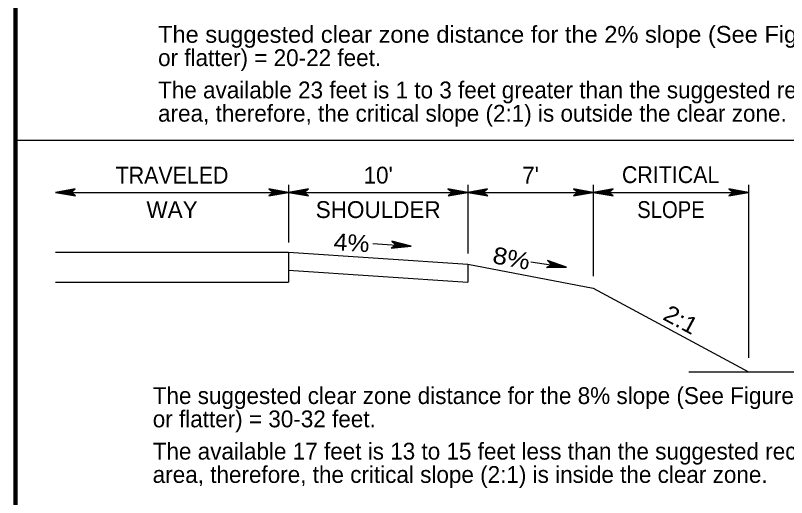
# Model space of a CAD drawing. Extents: x -15.691 to -15.016, y -14.8 to -13.916.
# Drawn here: x -15.6451 to -15.2866, y -14.3626 to -14.1387 of the extents above; entities that cross this region are included whole.
import ezdxf
from ezdxf.enums import TextEntityAlignment as Align

# ---------------------------------------------------------------- set-up
doc = ezdxf.new("R2010")
doc.units = 0
doc.header["$LTSCALE"] = 0.0031
for name, color, linetype, lineweight in [('1', 7, 'Continuous', 90), ('24', 7, 'Continuous', 25), ('5', 7, 'Continuous', 25)]:
    doc.layers.add(name, color=color, linetype=linetype, lineweight=lineweight)

msp = doc.modelspace()

# ---------------------------------------------------------------- linework, layer by layer
at = {"layer": '1'}
msp.add_line((-15.645142, -14.753775), (-15.645142, -13.962108), dxfattribs=at)
msp.add_line((-15.645142, -14.753775), (-15.645142, -13.962108), dxfattribs=at)
at = {"layer": '24'}
for p, q in [((-15.518158, -14.217367), (-15.518158, -14.244108)), ((-15.434825, -14.217367), (-15.434825, -14.249208)), ((-15.376492, -14.217367), (-15.376492, -14.259825)), ((-15.304267, -14.217367), (-15.304267, -14.297608)), ((-15.626492, -14.220833), (-15.518158, -14.220833)), ((-15.478925, -14.244533), (-15.4611, -14.245808)), ((-15.405475, -14.253025), (-15.388925, -14.255617))]:
    msp.add_line(p, q, dxfattribs=at)
for points in [[(-15.626492, -14.220833), (-15.61725, -14.222467), (-15.619458, -14.220833), (-15.6173, -14.219225), (-15.626492, -14.220833), (-15.625875, -14.220817), (-15.617508, -14.222342), (-15.619633, -14.220817), (-15.617675, -14.21935), (-15.62555, -14.220783), (-15.625242, -14.220833), (-15.618075, -14.222108), (-15.619683, -14.220817), (-15.618025, -14.219558), (-15.6251, -14.220833), (-15.624792, -14.220783), (-15.618525, -14.221917), (-15.619742, -14.220833), (-15.6185, -14.219708), (-15.6239, -14.220783), (-15.623375, -14.220783), (-15.618992, -14.221683), (-15.619842, -14.220858), (-15.618925, -14.219942), (-15.623283, -14.220833), (-15.622792, -14.220858), (-15.619492, -14.221425), (-15.620125, -14.220783), (-15.619442, -14.22015), (-15.622342, -14.220833), (-15.621875, -14.220883), (-15.619892, -14.221258), (-15.620217, -14.220817), (-15.619675, -14.220317), (-15.621633, -14.220833), (-15.620342, -14.221142), (-15.620525, -14.220783), (-15.619958, -14.220433), (-15.621308, -14.220783), (-15.620458, -14.221), (-15.620817, -14.220717), (-15.620408, -14.22055), (-15.620817, -14.220817), (-15.6206, -14.220858)], [(-15.518158, -14.220833), (-15.5274, -14.2192), (-15.525192, -14.220833), (-15.52735, -14.222442), (-15.518158, -14.220833), (-15.518775, -14.22085), (-15.527142, -14.219317), (-15.525017, -14.22085), (-15.526975, -14.222317), (-15.5191, -14.220875), (-15.519408, -14.220833), (-15.526583, -14.219558), (-15.524975, -14.22085), (-15.526625, -14.222108), (-15.51955, -14.220833), (-15.519858, -14.220875), (-15.526125, -14.21975), (-15.524908, -14.220833), (-15.52615, -14.221958), (-15.52075, -14.220883), (-15.521275, -14.220875), (-15.525658, -14.219983), (-15.524808, -14.220808), (-15.525725, -14.221725), (-15.521367, -14.220833), (-15.521858, -14.220808), (-15.525158, -14.220242), (-15.524525, -14.220883), (-15.525208, -14.221508), (-15.522317, -14.220833), (-15.522775, -14.220783), (-15.524758, -14.220408), (-15.524433, -14.22085), (-15.524975, -14.22135), (-15.523017, -14.220833), (-15.524308, -14.220525), (-15.524125, -14.220875), (-15.524692, -14.221233), (-15.523342, -14.220883), (-15.524192, -14.220667), (-15.523833, -14.22095), (-15.524242, -14.221117), (-15.523842, -14.22085), (-15.52405, -14.220808)], [(-15.518158, -14.220833), (-15.508917, -14.222467), (-15.511125, -14.220833), (-15.508967, -14.219225), (-15.518158, -14.220833), (-15.517542, -14.220817), (-15.509175, -14.222342), (-15.5113, -14.220817), (-15.509342, -14.21935), (-15.517217, -14.220783), (-15.516908, -14.220833), (-15.509742, -14.222108), (-15.51135, -14.220817), (-15.509692, -14.219558), (-15.516767, -14.220833), (-15.516458, -14.220783), (-15.510192, -14.221917), (-15.511408, -14.220833), (-15.510167, -14.219708), (-15.515567, -14.220783), (-15.515042, -14.220783), (-15.510658, -14.221683), (-15.511508, -14.220858), (-15.510592, -14.219942), (-15.51495, -14.220833), (-15.514458, -14.220858), (-15.511158, -14.221425), (-15.511792, -14.220783), (-15.511108, -14.22015), (-15.514008, -14.220833), (-15.513542, -14.220883), (-15.511558, -14.221258), (-15.511883, -14.220817), (-15.511342, -14.220317), (-15.5133, -14.220833), (-15.512008, -14.221142), (-15.512192, -14.220783), (-15.511625, -14.220433), (-15.512975, -14.220783), (-15.512125, -14.221), (-15.512483, -14.220717), (-15.512075, -14.22055), (-15.512475, -14.220817), (-15.512267, -14.220858)], [(-15.518158, -14.220833), (-15.434825, -14.220833), (-15.376492, -14.220833), (-15.304267, -14.220833)], [(-15.434825, -14.220833), (-15.444067, -14.2192), (-15.441858, -14.220833), (-15.444017, -14.222442), (-15.434825, -14.220833), (-15.435442, -14.22085), (-15.443808, -14.219317), (-15.441683, -14.22085), (-15.443642, -14.222317), (-15.435767, -14.220875), (-15.436075, -14.220833), (-15.44325, -14.219558), (-15.441642, -14.22085), (-15.443292, -14.222108), (-15.436217, -14.220833), (-15.436525, -14.220875), (-15.442792, -14.21975), (-15.441575, -14.220833), (-15.442817, -14.221958), (-15.437417, -14.220883), (-15.437942, -14.220875), (-15.442325, -14.219983), (-15.441475, -14.220808), (-15.442392, -14.221725), (-15.438033, -14.220833), (-15.438525, -14.220808), (-15.441825, -14.220242), (-15.441192, -14.220883), (-15.441875, -14.221508), (-15.438983, -14.220833), (-15.439442, -14.220783), (-15.441425, -14.220408), (-15.4411, -14.22085), (-15.441642, -14.22135), (-15.439683, -14.220833), (-15.440975, -14.220525), (-15.440792, -14.220875), (-15.441358, -14.221233), (-15.440008, -14.220883), (-15.440858, -14.220667), (-15.4405, -14.22095), (-15.440908, -14.221117), (-15.440508, -14.22085), (-15.440717, -14.220808)], [(-15.434825, -14.220833), (-15.425583, -14.222467), (-15.427792, -14.220833), (-15.425633, -14.219225), (-15.434825, -14.220833), (-15.434208, -14.220817), (-15.425842, -14.222342), (-15.427967, -14.220817), (-15.426008, -14.21935), (-15.433883, -14.220783), (-15.433575, -14.220833), (-15.426408, -14.222108), (-15.428017, -14.220817), (-15.426358, -14.219558), (-15.433433, -14.220833), (-15.433125, -14.220783), (-15.426858, -14.221917), (-15.428075, -14.220833), (-15.426833, -14.219708), (-15.432233, -14.220783), (-15.431708, -14.220783), (-15.427325, -14.221683), (-15.428175, -14.220858), (-15.427258, -14.219942), (-15.431617, -14.220833), (-15.431125, -14.220858), (-15.427825, -14.221425), (-15.428458, -14.220783), (-15.427775, -14.22015), (-15.430675, -14.220833), (-15.430208, -14.220883), (-15.428225, -14.221258), (-15.42855, -14.220817), (-15.428008, -14.220317), (-15.429967, -14.220833), (-15.428675, -14.221142), (-15.428858, -14.220783), (-15.428292, -14.220433), (-15.429642, -14.220783), (-15.428792, -14.221), (-15.42915, -14.220717), (-15.428742, -14.22055), (-15.429142, -14.220817), (-15.428933, -14.220858)], [(-15.376492, -14.220833), (-15.385733, -14.2192), (-15.383525, -14.220833), (-15.385683, -14.222442), (-15.376492, -14.220833), (-15.377108, -14.22085), (-15.385475, -14.219317), (-15.38335, -14.22085), (-15.385308, -14.222317), (-15.377433, -14.220875), (-15.377742, -14.220833), (-15.384917, -14.219558), (-15.383308, -14.22085), (-15.384958, -14.222108), (-15.377883, -14.220833), (-15.378192, -14.220875), (-15.384458, -14.21975), (-15.383242, -14.220833), (-15.384483, -14.221958), (-15.379083, -14.220883), (-15.379608, -14.220875), (-15.383992, -14.219983), (-15.383142, -14.220808), (-15.384058, -14.221725), (-15.3797, -14.220833), (-15.380192, -14.220808), (-15.383492, -14.220242), (-15.382858, -14.220883), (-15.383542, -14.221508), (-15.38065, -14.220833), (-15.381108, -14.220783), (-15.383092, -14.220408), (-15.382767, -14.22085), (-15.383308, -14.22135), (-15.38135, -14.220833), (-15.382642, -14.220525), (-15.382458, -14.220875), (-15.383025, -14.221233), (-15.381675, -14.220883), (-15.382525, -14.220667), (-15.382167, -14.22095), (-15.382575, -14.221117), (-15.382175, -14.22085), (-15.382383, -14.220808)], [(-15.376492, -14.220833), (-15.36725, -14.222467), (-15.369458, -14.220833), (-15.3673, -14.219225), (-15.376492, -14.220833), (-15.375875, -14.220817), (-15.367508, -14.222342), (-15.369633, -14.220817), (-15.367675, -14.21935), (-15.37555, -14.220783), (-15.375242, -14.220833), (-15.368075, -14.222108), (-15.369683, -14.220817), (-15.368025, -14.219558), (-15.3751, -14.220833), (-15.374792, -14.220783), (-15.368525, -14.221917), (-15.369742, -14.220833), (-15.3685, -14.219708), (-15.3739, -14.220783), (-15.373375, -14.220783), (-15.368992, -14.221683), (-15.369842, -14.220858), (-15.368925, -14.219942), (-15.373283, -14.220833), (-15.372792, -14.220858), (-15.369492, -14.221425), (-15.370125, -14.220783), (-15.369442, -14.22015), (-15.372342, -14.220833), (-15.371875, -14.220883), (-15.369892, -14.221258), (-15.370217, -14.220817), (-15.369675, -14.220317), (-15.371633, -14.220833), (-15.370342, -14.221142), (-15.370525, -14.220783), (-15.369958, -14.220433), (-15.371308, -14.220783), (-15.370458, -14.221), (-15.370817, -14.220717), (-15.370408, -14.22055), (-15.370808, -14.220817), (-15.3706, -14.220858)], [(-15.304267, -14.220833), (-15.313508, -14.2192), (-15.3113, -14.220833), (-15.313467, -14.222442), (-15.304267, -14.220833), (-15.304883, -14.22085), (-15.31325, -14.219317), (-15.311133, -14.22085), (-15.313092, -14.222317), (-15.305217, -14.220875), (-15.305525, -14.220833), (-15.312692, -14.219558), (-15.311083, -14.22085), (-15.312733, -14.222108), (-15.305667, -14.220833), (-15.305967, -14.220875), (-15.312233, -14.21975), (-15.311017, -14.220833), (-15.312258, -14.221958), (-15.306867, -14.220883), (-15.307383, -14.220875), (-15.311775, -14.219983), (-15.310917, -14.220808), (-15.311833, -14.221725), (-15.307475, -14.220833), (-15.307975, -14.220808), (-15.311267, -14.220242), (-15.310633, -14.220883), (-15.311325, -14.221508), (-15.308425, -14.220833), (-15.308892, -14.220783), (-15.310867, -14.220408), (-15.310542, -14.22085), (-15.311083, -14.22135), (-15.309133, -14.220833), (-15.310425, -14.220525), (-15.310233, -14.220875), (-15.3108, -14.221233), (-15.309458, -14.220883), (-15.3103, -14.220667), (-15.30995, -14.22095), (-15.310358, -14.221117), (-15.30995, -14.22085), (-15.310167, -14.220808)], [(-15.4611, -14.245808), (-15.4702, -14.243525), (-15.468108, -14.245308), (-15.470383, -14.246758), (-15.4611, -14.245808), (-15.461708, -14.245783), (-15.46995, -14.243658), (-15.467942, -14.245342), (-15.47, -14.246658), (-15.462042, -14.245792), (-15.46235, -14.245725), (-15.469408, -14.243942), (-15.467892, -14.245342), (-15.469633, -14.246475), (-15.462483, -14.245708), (-15.4628, -14.245733), (-15.468967, -14.244158), (-15.467825, -14.245333), (-15.46915, -14.246367), (-15.463683, -14.245675), (-15.464208, -14.245633), (-15.468517, -14.244425), (-15.467725, -14.245308), (-15.468708, -14.246158), (-15.464292, -14.245583), (-15.464783, -14.245517), (-15.468033, -14.244717), (-15.46745, -14.245408), (-15.468183, -14.245983), (-15.465242, -14.245517), (-15.4657, -14.245433), (-15.46765, -14.244917), (-15.467358, -14.245383), (-15.467933, -14.245833), (-15.465942, -14.245467), (-15.467208, -14.245067), (-15.46705, -14.245433), (-15.467642, -14.245742), (-15.466275, -14.245492), (-15.4671, -14.245217), (-15.466767, -14.245517), (-15.467183, -14.245658), (-15.466767, -14.245425), (-15.466975, -14.245367)], [(-15.388917, -14.255575), (-15.3978, -14.252533), (-15.395867, -14.254492), (-15.39825, -14.255742), (-15.388917, -14.255575), (-15.389533, -14.2555), (-15.397558, -14.252692), (-15.3957, -14.254533), (-15.397858, -14.255675), (-15.389858, -14.255475), (-15.390158, -14.255383), (-15.397042, -14.253017), (-15.39565, -14.254542), (-15.397483, -14.255525), (-15.3903, -14.255358), (-15.390608, -14.255358), (-15.396625, -14.253275), (-15.395583, -14.254533), (-15.396992, -14.255458), (-15.391492, -14.255225), (-15.392, -14.255142), (-15.3962, -14.253575), (-15.395483, -14.254525), (-15.396533, -14.255292), (-15.392092, -14.255083), (-15.392575, -14.254975), (-15.395742, -14.253908), (-15.395217, -14.254642), (-15.395992, -14.255158), (-15.393025, -14.254933), (-15.393475, -14.254817), (-15.395375, -14.254133), (-15.395125, -14.254625), (-15.395733, -14.255033), (-15.393725, -14.254825), (-15.39495, -14.254325), (-15.394825, -14.2547), (-15.395433, -14.254958), (-15.39405, -14.254825), (-15.394858, -14.254483), (-15.39455, -14.254808), (-15.394975, -14.254917), (-15.394533, -14.254717), (-15.394742, -14.254642)]]:
    msp.add_lwpolyline(points, dxfattribs=at)
at = {"layer": '5'}
for p, q in [((-15.645142, -14.196558), (-15.061808, -14.196558)), ((-15.626492, -14.248608), (-15.518158, -14.248608)), ((-15.518158, -14.248608), (-15.518158, -14.2625)), ((-15.434825, -14.254167), (-15.434825, -14.262517)), ((-15.518158, -14.256958), (-15.434825, -14.262517)), ((-15.626492, -14.2625), (-15.518158, -14.2625)), ((-15.33205, -14.304167), (-15.304267, -14.304167)), ((-15.304267, -14.304167), (-15.276492, -14.304167))]:
    msp.add_line(p, q, dxfattribs=at)
msp.add_lwpolyline([(-15.518158, -14.248608), (-15.434825, -14.254167), (-15.376492, -14.265275), (-15.304267, -14.304167)], dxfattribs=at)

# ---------------------------------------------------------------- texts
at = {"layer": '1', "width": 1.05}
msp.add_text('The suggested clear zone distance for the 2% slope (See Figure 8-A, Cut Slope, 6:1', height=0.007817, dxfattribs=at).set_placement((-15.578825, -14.151367))
at = {"layer": '1'}
for s, p in [('or flatter) = 20-22 feet.', (-15.578825, -14.162183)), ('The available 23 feet is 1 to 3 feet greater than the suggested recovery', (-15.578825, -14.177183)), ('area, therefore, the critical slope (2:1) is outside the clear zone.', (-15.578825, -14.188)), ('The suggested clear zone distance for the 8% slope (See Figure 8-A, Fill Slope, 6:1', (-15.581308, -14.319125)), ('or flatter) = 30-32 feet.', (-15.581308, -14.329942)), ('The available 17 feet is 13 to 15 feet less than the suggested recovery', (-15.581308, -14.344942)), ('area, therefore, the critical slope (2:1) is inside the clear zone.', (-15.581308, -14.355758))]:
    msp.add_text(s, height=0.007817, dxfattribs=at).set_placement(p)
for s, width, p in [('TRAVELED', 0.95, (-15.572321, -14.216742)), ('CRITICAL', 0.95, (-15.340533, -14.216517)), ('SLOPE', 0.9, (-15.340383, -14.232742))]:
    msp.add_text(s, height=0.007817, dxfattribs=dict(at, width=width)).set_placement(p, align=Align.CENTER)
for s, p in [("10'", (-15.476496, -14.216742)), ("7'", (-15.405658, -14.216742)), ('WAY', (-15.572321, -14.232742)), ('SHOULDER', (-15.476496, -14.232742))]:
    msp.add_text(s, height=0.007817, dxfattribs=at).set_placement(p, align=Align.CENTER)
for s, rotation, width, p in [('4%', 356.566, 1.1, (-15.489076, -14.248111)), ('8%', 349.216, 1.15, (-15.41524, -14.255238)), ('2:1', 331.699, 1.1, (-15.33762, -14.283396))]:
    msp.add_text(s, height=0.007817, rotation=rotation, dxfattribs=dict(at, width=width)).set_placement(p, align=Align.CENTER)

doc.saveas('drawing.dxf')
